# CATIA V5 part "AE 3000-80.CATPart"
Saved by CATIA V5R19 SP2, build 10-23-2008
Part number: AE 3000-80
Bounding box of the stored display mesh (mm): x -47.487 to 47.487, y -47.487 to 47.487, z 0 to 230
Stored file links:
  C:\Users\Bora\Desktop\3D Katı model\AE serisi\AE 3000\AE 3000-80.CATPart
  C:\Program Files\Dassault Systemes\B19\intel_a\reffiles\standard\MetricThickPitch.txt
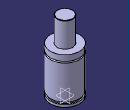
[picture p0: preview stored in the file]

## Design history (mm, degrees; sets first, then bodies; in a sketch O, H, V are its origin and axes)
Body1 (main body)
  Sketch1 on yz-plane, origin (0, 0, 0), H (0, 1, 0), V (0, 0, 1)
    point P1 (47.5, 130.5)
    point P5 (25, 229)
    point P7 (25, 229)
    point P12 (47.5, 125.5)
    point P13 (47.5, 130.5)
    point P14 (47.5, 125.5)
    line L1 (47.5, 130.5) -> (47.5, 149)
    line L2 (47.5, 0) -> (47.5, 8)
    arc A1 centre (24, 229) radius 1 from (25, 229) to (24, 230) ccw
    line L3 (25, 229) -> (25, 149)
    line L4 (43.5, 15) -> (43.5, 8)
    line L5 (47.5, 15) -> (47.5, 125.5)
    arc A2 centre (47.5, 128) radius 2.5 from (47.5, 130.5) to (47.5, 125.5) ccw
    line L6 (24, 230) -> (0, 230)
    point P15 (0, 230)
    line L7 (25, 149) -> (47.5, 149)
    line L8 (0, 0) -> (47.5, 0)
    line L9 (43.5, 15) -> (47.5, 15)
    line L10 (43.5, 8) -> (47.5, 8)
    coincidence: P15 V, P1 P13, P5 P7, P12 P14
    tangency: L6 A1
    horizontal: L7 H, L8 H, L9 H, L10 H
  Shaft1: profile Sketch1, axis Sketch1.V, angle 360
  Sketch2 on face of Shaft1 from Sketch1.L8, origin (0, 0, 0), H (1, 0, 0), V (0, -1, 0)
    point P1 (30, 0)
    distance P1 V = 30
  Hole1: placed by Sketch2, at (30, 0, 0) direction (0, 0, 1), diameter 6.647, depth 13, threaded "M8", thread diameter 8, thread depth 13, pitch 1.25
  CircPattern1: of Hole1, instances 4, angular step 90, axis from xy-plane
